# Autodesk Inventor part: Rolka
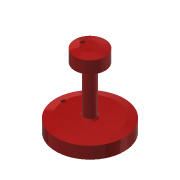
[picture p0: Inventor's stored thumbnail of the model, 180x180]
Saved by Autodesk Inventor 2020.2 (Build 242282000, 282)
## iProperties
Created: 2005-12
Part Number: Rolka
Document SubType Name: Modeling
Designer: F.Stasiak
Density: 1 g/cm^3
Material: Ogólny
Appearance: Gładkie — czerwone
Manager: www.cadconsulting.pl
Company: Fabian Stasiak CAD Consulting
Author: F.Stasiak
Subject: Zbiór ćwiczeń. Autodesk Inventor 2020. Kurs podstawowy
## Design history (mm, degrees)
sketch "Szkic1"
  geometry: C1 r 45 at (0, 0); 1 further point
  constraints: 1 centre point, 1 coincident
  dimensions: "d0" = 90 diameter of C1
extrude "Wyciągnięcie proste1" new body sketch "Szkic1" distance "d1" = 20; taper "d2" = 0 deg
chamfer "Faza1" distance "d3" = 2; stored, may be unused: second distance "d4" = 10, angle "d5" = 45 deg
chamfer "Faza2" distance "d6" = 2; stored, may be unused: second distance "d7" = 10, angle "d8" = 45 deg
sketch "Szkic2"
  geometry: C1 r 3 at (-35, -0.143); 1 further point
  constraints: 1 centre point, 2 other
  dimensions: "d9" = 6 diameter of C1
extrude "Wyciągnięcie proste2" cut sketch "Szkic2" stored distance "d10" = 20; taper "d11" = 0 deg
sketch "Szkic3"
  geometry: C1 r 7.5 at (0, 0); A1 r 35 centre (0, 0) between (-34.859, -3.14) and (-34.883, 2.854) reference
  constraints: 1 centre point, 1 coincident
  dimensions: "d12" = 15 diameter of C1
extrude "Wyciągnięcie proste3" join sketch "Szkic3" distance "d13" = 80; taper "d14" = 0 deg
chamfer "Faza3" distance "d15" = 2; stored, may be unused: second distance "d16" = 10, angle "d17" = 45 deg
sketch "Szkic4"
  geometry: C1 r 7.5 at (0, 0) reference; C2 r 20 at (0, 0)
  constraints: 1 centre point, 1 coincident
  dimensions: "d18" = 40 diameter of C2
extrude "Wyciągnięcie proste4" join sketch "Szkic4" distance "d19" = 20; taper "d20" = 0 deg
chamfer "Faza4" distance "d21" = 2; stored, may be unused: second distance "d22" = 10, angle "d23" = 45 deg
chamfer "Faza5" distance "d24" = 2; stored, may be unused: second distance "d25" = 10, angle "d26" = 45 deg
sketch "Szkic5"
  geometry: L1 (0, 0)-(-10, 0); C1 r 3 at (-10, 0)
  constraints: 2 end point, 1 centre point, 1 coincident, 1 horizontal, 1 horizontal alignment, 1 other
  dimensions: "d27" = 6 diameter of C1
extrude "Wyciągnięcie proste5" cut sketch "Szkic5" stored distance "d28" = 20; taper "d29" = 0 deg
node "Bryła1"
node "Korpusy bryłowe"
node "Korpusy powierzchniowe"
